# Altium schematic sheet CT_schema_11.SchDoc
size 387 x 278 mm
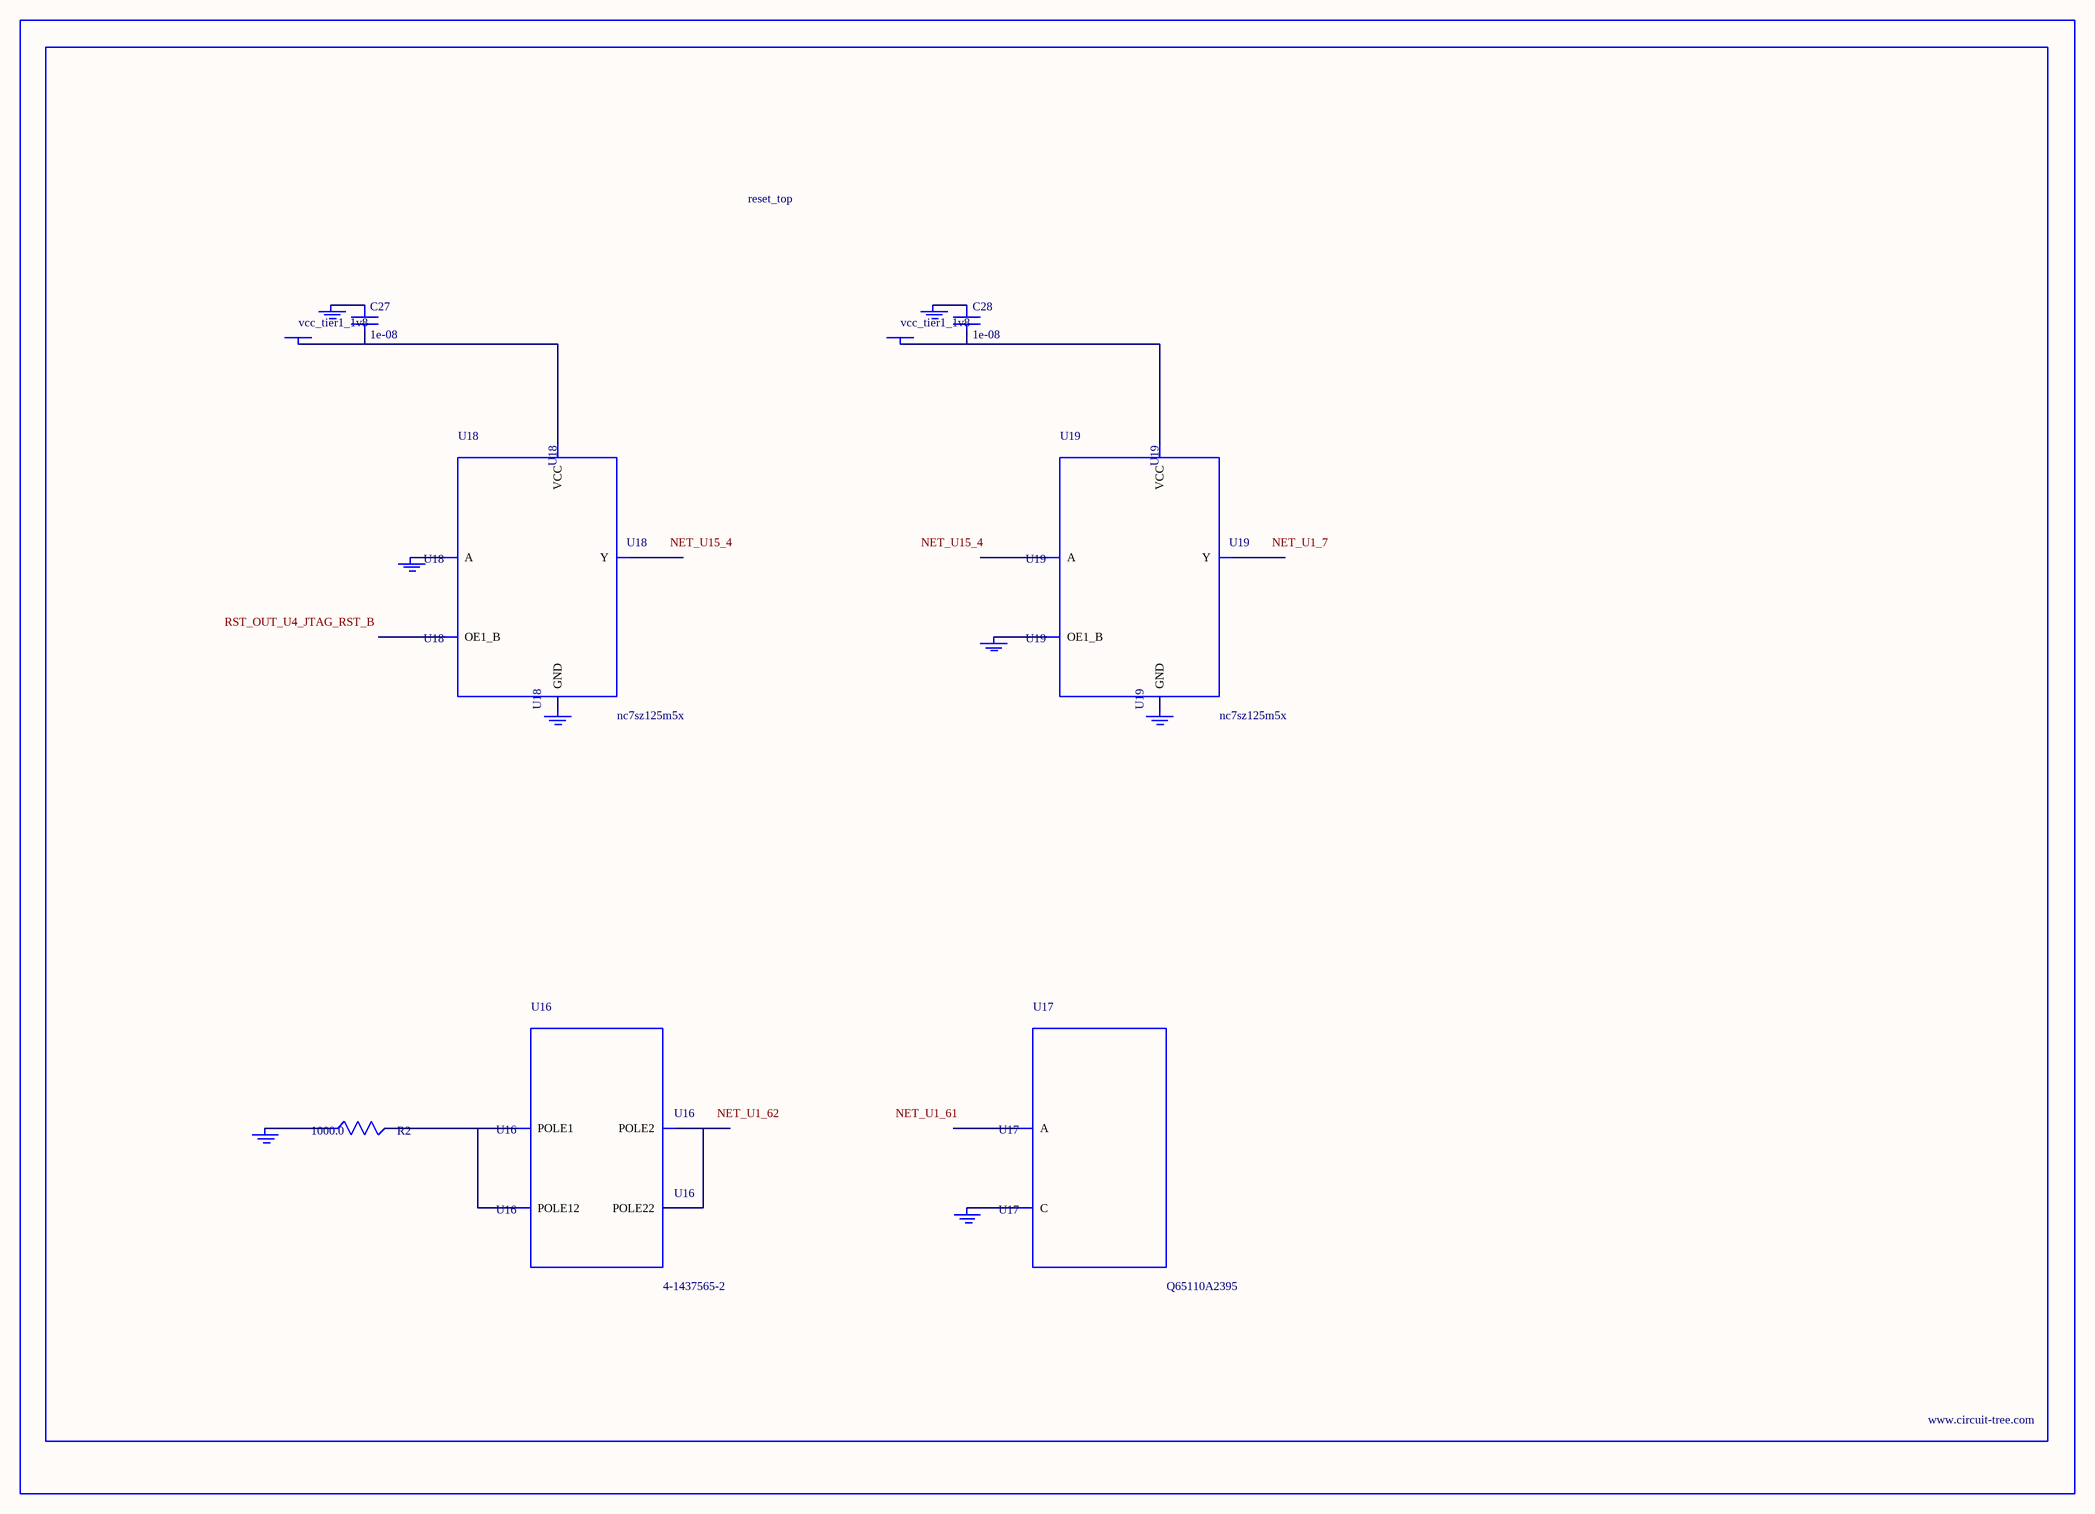
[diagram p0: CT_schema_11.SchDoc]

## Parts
BORDER10  (no value)
C27  1e-08  [C0402]
C28  1e-08  [C0402]
GND_INSTANCE_10_0  (no value)
GND_INSTANCE_10_1  (no value)
GND_INSTANCE_10_2  (no value)
GND_INSTANCE_10_3  (no value)
GND_INSTANCE_10_4  (no value)
GND_INSTANCE_10_5  (no value)
GND_INSTANCE_10_6  (no value)
GND_INSTANCE_10_7  (no value)
POWER_INSTANCE_10_0  vcc_tier1_1v8
POWER_INSTANCE_10_1  vcc_tier1_1v8
R2  1000.0  [R0603]
U16  4-1437565-2  [SW_4-1437565-2]
U17  Q65110A2395  [LGM67K-G1J2-24-Z]
U18  nc7sz125m5x  [NC7SZ125M5X]
U19  nc7sz125m5x  [NC7SZ125M5X]

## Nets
NetC27_1: C27.1 GND_INSTANCE_10_2.0(GND)
NetC27_2: C27.2 POWER_INSTANCE_10_0.0(PWR) U18.5(VCC)
NetC28_1: C28.1 GND_INSTANCE_10_5.0(GND)
NetC28_2: C28.2 POWER_INSTANCE_10_1.0(PWR) U19.5(VCC)
NetGND_INSTANCE_10_0_0: GND_INSTANCE_10_0.0(GND) R2.1
NetGND_INSTANCE_10_1_0: GND_INSTANCE_10_1.0(GND) U17.C
NetGND_INSTANCE_10_3_0: GND_INSTANCE_10_3.0(GND) U18.2(A)
NetGND_INSTANCE_10_4_0: GND_INSTANCE_10_4.0(GND) U18.3(GND)
NetGND_INSTANCE_10_6_0: GND_INSTANCE_10_6.0(GND) U19.1(OE1_B)
NetGND_INSTANCE_10_7_0: GND_INSTANCE_10_7.0(GND) U19.3(GND)
NetR2_2: R2.2 U16.1(POLE1) U16.2(POLE12)
NetU16_3: U16.3(POLE2) U16.4(POLE22)

Not connected (* = marked no-connect by the designer): U17 A; U18 1(OE1_B) 4(Y); U19 2(A) 4(Y)

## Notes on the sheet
- Labels drawn without touching a wire or pin: NET_U1_7, NET_U1_61, NET_U1_62, NET_U15_4, RST_OUT_U4_JTAG_RST_B

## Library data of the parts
BORDER10 = BORDER_PAGE10
C27 C28 = C0402C103K3RAC
GND_INSTANCE_10_0-GND_INSTANCE_10_7 = GND
POWER_INSTANCE_10_0 POWER_INSTANCE_10_1 = PWR
R2 = RC0603JR-071KL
